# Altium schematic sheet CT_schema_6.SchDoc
size 255 x 245 mm
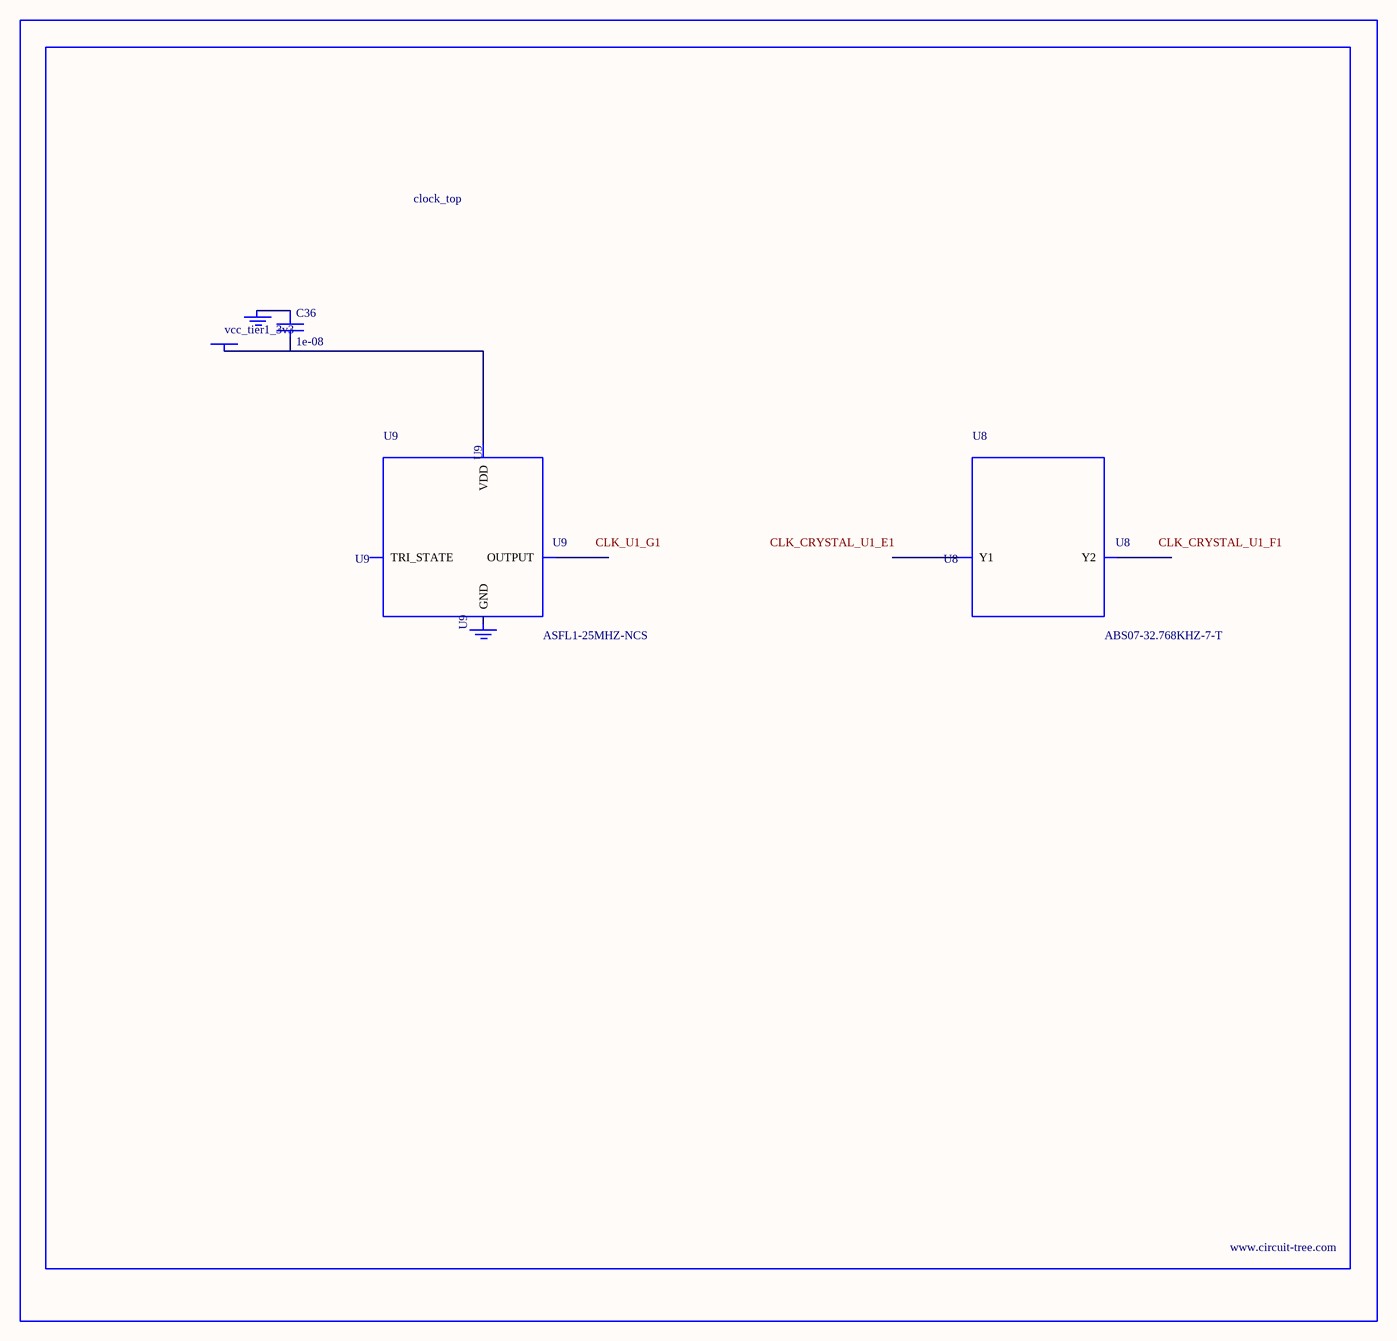
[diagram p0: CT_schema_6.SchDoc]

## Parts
BORDER5  (no value)
C36  1e-08  [C0402]
GND_INSTANCE_5_0  (no value)
GND_INSTANCE_5_1  (no value)
POWER_INSTANCE_5_0  vcc_tier1_3v3
U8  ABS07-32.768KHZ-7-T  [ABS07-32.768KHZ-7-T]
U9  ASFL1-25MHZ-NCS  [ASFL1]

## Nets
NetC36_1: C36.1 GND_INSTANCE_5_0.0(GND)
NetC36_2: C36.2 POWER_INSTANCE_5_0.0(PWR) U9.4(VDD)

Not connected (* = marked no-connect by the designer): GND_INSTANCE_5_1 0(GND); U8 1(Y1) 2(Y2); U9 1(TRI_STATE) 2(GND) 3(OUTPUT)

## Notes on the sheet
- Labels drawn without touching a wire or pin: CLK_CRYSTAL_U1_E1, CLK_CRYSTAL_U1_F1, CLK_U1_G1

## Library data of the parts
BORDER5 = BORDER_PAGE5
C36 = C0402C103K3RAC
GND_INSTANCE_5_0 GND_INSTANCE_5_1 = GND
POWER_INSTANCE_5_0 = PWR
